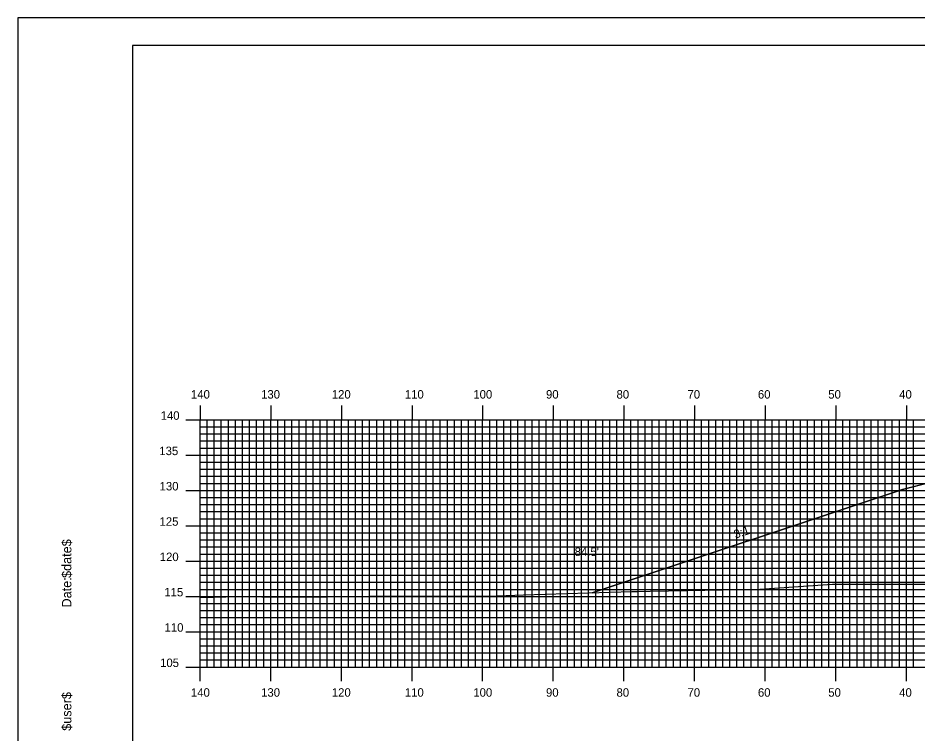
# Model space of a CAD drawing. Extents: x 1788943 to 1789287, y 442591 to 442811.
# Drawn here: x 1788943.4 to 1789070.7, y 442709.3 to 442810.5 of the extents above; entities that cross this region are included whole.
import ezdxf

# ---------------------------------------------------------------- set-up
doc = ezdxf.new("R2010")
doc.units = 0
for name, color, linetype in [('ANNOTATION', 7, 'Continuous'), ('BORDER', 7, 'Continuous'), ('D_Roadway_Centerline', 7, 'Continuous'), ('D_Roadway_SlopeLines', 7, 'Continuous'), ('D_Text_Standard', 7, 'Continuous'), ('H_V ANNOTATION', 7, 'Continuous'), ('MAJOR', 7, 'Continuous'), ('MINOR', 7, 'Continuous'), ('PLOT BOUNDARY', 7, 'Continuous'), ('S_Roadway_Centerline', 7, 'Continuous')]:
    doc.layers.add(name, color=color, linetype=linetype)

msp = doc.modelspace()

# ---------------------------------------------------------------- linework, layer by layer
at = {"layer": 'BORDER'}
msp.add_lwpolyline([(1788959.56, 442596.67), (1789279.56, 442596.67), (1789279.56, 442806.67), (1788959.56, 442806.67)], close=True, dxfattribs=at)
at = {"layer": 'D_Roadway_Centerline'}
msp.add_lwpolyline([(1789024.64, 442729.16), (1789068.59, 442743.81), (1789071.16, 442744.45), (1789080.59, 442746.81), (1789097.16, 442747.47), (1789109.16, 442747.74), (1789121.16, 442748), (1789129.16, 442747.68), (1789132.16, 442747.56), (1789139.43, 442745.14), (1789179.89, 442731.65)], dxfattribs=at)
at = {"layer": 'D_Roadway_SlopeLines'}
msp.add_lwpolyline([(1789080.59, 442746.81), (1789068.59, 442743.81), (1789024.64, 442729.16)], dxfattribs=at)
at = {"layer": 'MAJOR'}
for p, q in [((1788969.16, 442755.67), (1788969.16, 442753.67)), ((1788979.16, 442755.67), (1788979.16, 442753.67)), ((1788989.16, 442755.67), (1788989.16, 442753.67)), ((1788999.16, 442755.67), (1788999.16, 442753.67)), ((1789009.16, 442755.67), (1789009.16, 442753.67)), ((1789019.16, 442755.67), (1789019.16, 442753.67)), ((1789029.16, 442755.67), (1789029.16, 442753.67)), ((1789039.16, 442755.67), (1789039.16, 442753.67)), ((1789049.16, 442755.67), (1789049.16, 442753.67)), ((1789059.16, 442755.67), (1789059.16, 442753.67)), ((1789069.16, 442755.67), (1789069.16, 442753.67)), ((1788967.15, 442753.67), (1788969.16, 442753.67)), ((1788969.16, 442753.67), (1789249.16, 442753.67)), ((1788969.16, 442718.67), (1788969.16, 442753.67)), ((1788969.16, 442718.67), (1788969.16, 442753.67)), ((1788969.16, 442753.67), (1789249.16, 442753.67)), ((1788979.16, 442718.67), (1788979.16, 442753.67)), ((1788989.16, 442718.67), (1788989.16, 442753.67)), ((1788999.16, 442718.67), (1788999.16, 442753.67)), ((1789009.16, 442718.67), (1789009.16, 442753.67)), ((1789019.16, 442718.67), (1789019.16, 442753.67)), ((1789029.16, 442718.67), (1789029.16, 442753.67)), ((1789039.16, 442718.67), (1789039.16, 442753.67)), ((1789049.16, 442718.67), (1789049.16, 442753.67)), ((1789059.16, 442718.67), (1789059.16, 442753.67)), ((1789069.16, 442718.67), (1789069.16, 442753.67)), ((1788967.15, 442748.67), (1788969.16, 442748.67)), ((1788969.16, 442748.67), (1789249.16, 442748.67)), ((1788967.15, 442743.67), (1788969.16, 442743.67)), ((1788969.16, 442743.67), (1789249.16, 442743.67)), ((1788967.15, 442738.67), (1788969.16, 442738.67)), ((1788969.16, 442738.67), (1789249.16, 442738.67)), ((1788967.15, 442733.67), (1788969.16, 442733.67)), ((1788969.16, 442733.67), (1789249.16, 442733.67)), ((1788967.15, 442728.67), (1788969.16, 442728.67)), ((1788969.16, 442728.67), (1789249.16, 442728.67)), ((1788967.15, 442723.67), (1788969.16, 442723.67)), ((1788969.16, 442723.67), (1789249.16, 442723.67)), ((1788967.15, 442718.67), (1788969.16, 442718.67)), ((1788969.16, 442718.67), (1789249.16, 442718.67)), ((1788969.16, 442718.67), (1789249.16, 442718.67)), ((1788969.16, 442716.66), (1788969.16, 442718.67)), ((1788979.16, 442716.66), (1788979.16, 442718.67)), ((1788989.16, 442716.66), (1788989.16, 442718.67)), ((1788999.16, 442716.66), (1788999.16, 442718.67)), ((1789009.16, 442716.66), (1789009.16, 442718.67)), ((1789019.16, 442716.66), (1789019.16, 442718.67)), ((1789029.16, 442716.66), (1789029.16, 442718.67)), ((1789039.16, 442716.66), (1789039.16, 442718.67)), ((1789049.16, 442716.66), (1789049.16, 442718.67)), ((1789059.16, 442716.66), (1789059.16, 442718.67)), ((1789069.16, 442716.66), (1789069.16, 442718.67))]:
    msp.add_line(p, q, dxfattribs=at)
at = {"layer": 'MINOR'}
for p, q in [((1788969.16, 442752.67), (1789249.16, 442752.67)), ((1788969.16, 442752.67), (1788971.16, 442752.67)), ((1788970.16, 442718.67), (1788970.16, 442753.67)), ((1788971.16, 442718.67), (1788971.16, 442753.67)), ((1788972.16, 442718.67), (1788972.16, 442753.67)), ((1788973.16, 442718.67), (1788973.16, 442753.67)), ((1788974.16, 442718.67), (1788974.16, 442753.67)), ((1788975.16, 442718.67), (1788975.16, 442753.67)), ((1788976.16, 442718.67), (1788976.16, 442753.67)), ((1788977.16, 442718.67), (1788977.16, 442753.67)), ((1788978.16, 442718.67), (1788978.16, 442753.67)), ((1788980.16, 442718.67), (1788980.16, 442753.67)), ((1788981.16, 442718.67), (1788981.16, 442753.67)), ((1788982.16, 442718.67), (1788982.16, 442753.67)), ((1788983.16, 442718.67), (1788983.16, 442753.67)), ((1788984.16, 442718.67), (1788984.16, 442753.67)), ((1788985.16, 442718.67), (1788985.16, 442753.67)), ((1788986.16, 442718.67), (1788986.16, 442753.67)), ((1788987.16, 442718.67), (1788987.16, 442753.67)), ((1788988.16, 442718.67), (1788988.16, 442753.67)), ((1788990.16, 442718.67), (1788990.16, 442753.67)), ((1788991.16, 442718.67), (1788991.16, 442753.67)), ((1788992.16, 442718.67), (1788992.16, 442753.67)), ((1788993.16, 442718.67), (1788993.16, 442753.67)), ((1788994.16, 442718.67), (1788994.16, 442753.67)), ((1788995.16, 442718.67), (1788995.16, 442753.67)), ((1788996.16, 442718.67), (1788996.16, 442753.67)), ((1788997.16, 442718.67), (1788997.16, 442753.67)), ((1788998.16, 442718.67), (1788998.16, 442753.67)), ((1789000.16, 442718.67), (1789000.16, 442753.67)), ((1789001.16, 442718.67), (1789001.16, 442753.67)), ((1789002.16, 442718.67), (1789002.16, 442753.67)), ((1789003.16, 442718.67), (1789003.16, 442753.67)), ((1789004.16, 442718.67), (1789004.16, 442753.67)), ((1789005.16, 442718.67), (1789005.16, 442753.67)), ((1789006.16, 442718.67), (1789006.16, 442753.67)), ((1789007.16, 442718.67), (1789007.16, 442753.67)), ((1789008.16, 442718.67), (1789008.16, 442753.67)), ((1789010.16, 442718.67), (1789010.16, 442753.67)), ((1789011.16, 442718.67), (1789011.16, 442753.67)), ((1789012.16, 442718.67), (1789012.16, 442753.67)), ((1789013.16, 442718.67), (1789013.16, 442753.67)), ((1789014.16, 442718.67), (1789014.16, 442753.67)), ((1789015.16, 442718.67), (1789015.16, 442753.67)), ((1789016.16, 442718.67), (1789016.16, 442753.67)), ((1789017.16, 442718.67), (1789017.16, 442753.67)), ((1789018.16, 442718.67), (1789018.16, 442753.67)), ((1789020.16, 442718.67), (1789020.16, 442753.67)), ((1789021.16, 442718.67), (1789021.16, 442753.67)), ((1789022.16, 442718.67), (1789022.16, 442753.67)), ((1789023.16, 442718.67), (1789023.16, 442753.67)), ((1789024.16, 442718.67), (1789024.16, 442753.67)), ((1789025.16, 442718.67), (1789025.16, 442753.67)), ((1789026.16, 442718.67), (1789026.16, 442753.67)), ((1789027.16, 442718.67), (1789027.16, 442753.67)), ((1789028.16, 442718.67), (1789028.16, 442753.67)), ((1789030.16, 442718.67), (1789030.16, 442753.67)), ((1789031.16, 442718.67), (1789031.16, 442753.67)), ((1789032.16, 442718.67), (1789032.16, 442753.67)), ((1789033.16, 442718.67), (1789033.16, 442753.67)), ((1789034.16, 442718.67), (1789034.16, 442753.67)), ((1789035.16, 442718.67), (1789035.16, 442753.67)), ((1789036.16, 442718.67), (1789036.16, 442753.67)), ((1789037.16, 442718.67), (1789037.16, 442753.67)), ((1789038.16, 442718.67), (1789038.16, 442753.67)), ((1789040.16, 442718.67), (1789040.16, 442753.67)), ((1789041.16, 442718.67), (1789041.16, 442753.67)), ((1789042.16, 442718.67), (1789042.16, 442753.67)), ((1789043.16, 442718.67), (1789043.16, 442753.67)), ((1789044.16, 442718.67), (1789044.16, 442753.67)), ((1789045.16, 442718.67), (1789045.16, 442753.67)), ((1789046.16, 442718.67), (1789046.16, 442753.67)), ((1789047.16, 442718.67), (1789047.16, 442753.67)), ((1789048.16, 442718.67), (1789048.16, 442753.67)), ((1789050.16, 442718.67), (1789050.16, 442753.67)), ((1789051.16, 442718.67), (1789051.16, 442753.67)), ((1789052.16, 442718.67), (1789052.16, 442753.67)), ((1789053.16, 442718.67), (1789053.16, 442753.67)), ((1789054.16, 442718.67), (1789054.16, 442753.67)), ((1789055.16, 442718.67), (1789055.16, 442753.67)), ((1789056.16, 442718.67), (1789056.16, 442753.67)), ((1789057.16, 442718.67), (1789057.16, 442753.67)), ((1789058.16, 442718.67), (1789058.16, 442753.67)), ((1789060.16, 442718.67), (1789060.16, 442753.67)), ((1789061.16, 442718.67), (1789061.16, 442753.67)), ((1789062.16, 442718.67), (1789062.16, 442753.67)), ((1789063.16, 442718.67), (1789063.16, 442753.67)), ((1789064.16, 442718.67), (1789064.16, 442753.67)), ((1789065.16, 442718.67), (1789065.16, 442753.67)), ((1789066.16, 442718.67), (1789066.16, 442753.67)), ((1789067.16, 442718.67), (1789067.16, 442753.67)), ((1789068.16, 442718.67), (1789068.16, 442753.67)), ((1789070.16, 442718.67), (1789070.16, 442753.67)), ((1788969.16, 442751.67), (1789249.16, 442751.67)), ((1788969.16, 442751.67), (1788971.16, 442751.67)), ((1788969.16, 442750.67), (1789249.16, 442750.67)), ((1788969.16, 442750.67), (1788971.16, 442750.67)), ((1788969.16, 442749.67), (1789249.16, 442749.67)), ((1788969.16, 442749.67), (1788971.16, 442749.67)), ((1788969.16, 442747.67), (1789249.16, 442747.67)), ((1788969.16, 442747.67), (1788971.16, 442747.67)), ((1788969.16, 442746.67), (1789249.16, 442746.67)), ((1788969.16, 442746.67), (1788971.16, 442746.67)), ((1788969.16, 442745.67), (1789249.16, 442745.67)), ((1788969.16, 442745.67), (1788971.16, 442745.67)), ((1788969.16, 442744.67), (1789249.16, 442744.67)), ((1788969.16, 442744.67), (1788971.16, 442744.67)), ((1788969.16, 442742.67), (1789249.16, 442742.67)), ((1788969.16, 442742.67), (1788971.16, 442742.67)), ((1788969.16, 442741.67), (1789249.16, 442741.67)), ((1788969.16, 442741.67), (1788971.16, 442741.67)), ((1788969.16, 442740.67), (1789249.16, 442740.67)), ((1788969.16, 442740.67), (1788971.16, 442740.67)), ((1788969.16, 442739.67), (1789249.16, 442739.67)), ((1788969.16, 442739.67), (1788971.16, 442739.67)), ((1788969.16, 442737.67), (1789249.16, 442737.67)), ((1788969.16, 442737.67), (1788971.16, 442737.67)), ((1788969.16, 442736.67), (1789249.16, 442736.67)), ((1788969.16, 442736.67), (1788971.16, 442736.67)), ((1788969.16, 442735.67), (1789249.16, 442735.67)), ((1788969.16, 442735.67), (1788971.16, 442735.67)), ((1788969.16, 442734.67), (1789249.16, 442734.67)), ((1788969.16, 442734.67), (1788971.16, 442734.67)), ((1788969.16, 442732.67), (1789249.16, 442732.67)), ((1788969.16, 442732.67), (1788971.16, 442732.67)), ((1788969.16, 442731.67), (1789249.16, 442731.67)), ((1788969.16, 442731.67), (1788971.16, 442731.67)), ((1788969.16, 442730.67), (1789249.16, 442730.67)), ((1788969.16, 442730.67), (1788971.16, 442730.67)), ((1788969.16, 442729.67), (1789249.16, 442729.67)), ((1788969.16, 442729.67), (1788971.16, 442729.67)), ((1788969.16, 442727.67), (1789249.16, 442727.67)), ((1788969.16, 442727.67), (1788971.16, 442727.67)), ((1788969.16, 442726.67), (1789249.16, 442726.67)), ((1788969.16, 442726.67), (1788971.16, 442726.67)), ((1788969.16, 442725.67), (1789249.16, 442725.67)), ((1788969.16, 442725.67), (1788971.16, 442725.67)), ((1788969.16, 442724.67), (1789249.16, 442724.67)), ((1788969.16, 442724.67), (1788971.16, 442724.67)), ((1788969.16, 442722.67), (1789249.16, 442722.67)), ((1788969.16, 442722.67), (1788971.16, 442722.67)), ((1788969.16, 442721.67), (1789249.16, 442721.67)), ((1788969.16, 442721.67), (1788971.16, 442721.67)), ((1788969.16, 442720.67), (1789249.16, 442720.67)), ((1788969.16, 442720.67), (1788971.16, 442720.67)), ((1788969.16, 442719.67), (1789249.16, 442719.67)), ((1788969.16, 442719.67), (1788971.16, 442719.67))]:
    msp.add_line(p, q, dxfattribs=at)
at = {"layer": 'PLOT BOUNDARY'}
msp.add_lwpolyline([(1788943.37, 442590.55), (1789283.37, 442590.55), (1789283.37, 442810.55), (1788943.37, 442810.55)], close=True, dxfattribs=at)
at = {"layer": 'S_Roadway_Centerline'}
msp.add_lwpolyline([(1788969.16, 442728.52), (1788974.64, 442728.65), (1788981.16, 442728.58), (1788992.94, 442728.67), (1788993.18, 442728.68), (1789011.28, 442728.74), (1789014.93, 442728.87), (1789030.27, 442729.34), (1789031.21, 442729.36), (1789032.86, 442729.39), (1789048.42, 442729.68), (1789058.67, 442730.42), (1789075.08, 442730.42)], dxfattribs=at)

# ---------------------------------------------------------------- texts
at = {"layer": 'ANNOTATION'}
msp.add_text('3:1', height=1.2, rotation=18.4348, dxfattribs=at).set_placement((1789044.95, 442736.84))
at = {"layer": 'BORDER'}
for s, p in [('$date$', (1788950.93, 442731.28)), ('Date:', (1788950.93, 442727.1)), ('$user$', (1788950.93, 442709.65))]:
    msp.add_text(s, height=1.339, rotation=90, dxfattribs=at).set_placement(p)
at = {"layer": 'D_Text_Standard'}
msp.add_text("84.5'", height=1.2, dxfattribs=at).set_placement((1789022.18, 442734.39))
at = {"layer": 'H_V ANNOTATION'}
for s, p in [('140', (1788967.86, 442756.67)), ('130', (1788977.79, 442756.67)), ('120', (1788987.8, 442756.67)), ('110', (1788998.14, 442756.67)), ('100', (1789007.84, 442756.67)), ('90', (1789018.13, 442756.67)), ('80', (1789028.11, 442756.67)), ('70', (1789038.16, 442756.67)), ('60', (1789048.13, 442756.67)), ('50', (1789058.09, 442756.67)), ('40', (1789068.13, 442756.67)), ('140', (1788963.57, 442753.67)), ('135', (1788963.38, 442748.67)), ('130', (1788963.42, 442743.67)), ('125', (1788963.41, 442738.67)), ('120', (1788963.44, 442733.67)), ('115', (1788964.09, 442728.67)), ('110', (1788964.12, 442723.67)), ('105', (1788963.49, 442718.67)), ('140', (1788967.86, 442714.47)), ('130', (1788977.79, 442714.47)), ('120', (1788987.8, 442714.47)), ('110', (1788998.14, 442714.47)), ('100', (1789007.84, 442714.47)), ('90', (1789018.13, 442714.47)), ('80', (1789028.11, 442714.47)), ('70', (1789038.16, 442714.47)), ('60', (1789048.13, 442714.47)), ('50', (1789058.09, 442714.47)), ('40', (1789068.13, 442714.47))]:
    msp.add_text(s, height=1.2, dxfattribs=at).set_placement(p)
at = {"layer": 'MAJOR'}
msp.add_text('-', height=0.012, dxfattribs=at).set_placement((1788969.15, 442718.67))

doc.saveas('drawing.dxf')
